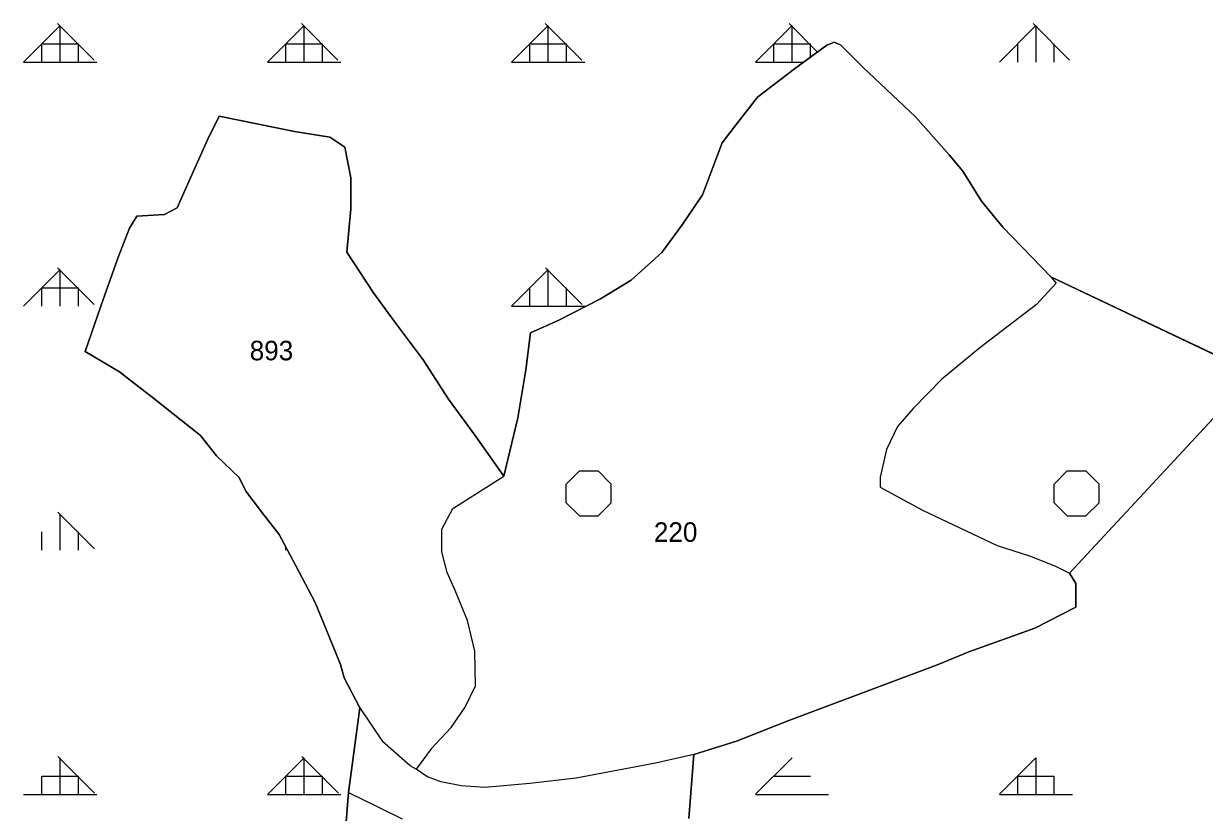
# Model space of a CAD drawing. Extents: x 410727 to 412947, y 4463506 to 4466382.
# Drawn here: x 412205.2 to 412447.2, y 4465932.2 to 4466093.7 of the extents above; entities that cross this region are included whole.
import ezdxf

# ---------------------------------------------------------------- set-up
doc = ezdxf.new("R2010")
doc.units = 0
for name, color, linetype in [('ADAKENARI', 7, 'Continuous'), ('KDS_PARSEL_NO', 7, 'Continuous'), ('KDS_PL', 7, 'Continuous'), ('PL_AYA_ORMAN', 7, 'Continuous'), ('PL_KA_TARIM_DIGER', 7, 'Continuous'), ('TR_ORMAN', 7, 'Continuous'), ('TR_TARIMALANI', 7, 'Continuous')]:
    doc.layers.add(name, color=color, linetype=linetype)

msp = doc.modelspace()

# ---------------------------------------------------------------- linework, layer by layer
at = {"layer": 'ADAKENARI'}
for p, q in [((412369.78, 4466089.3), (412363.17, 4466084.46)), ((412371.39, 4466089.94), (412369.78, 4466089.3)), ((412372.67, 4466089.3), (412371.39, 4466089.94)), ((412377.18, 4466084.78), (412372.67, 4466089.3)), ((412363.17, 4466084.46), (412355.6, 4466078.65)), ((412387.98, 4466074.61), (412377.18, 4466084.78)), ((412355.6, 4466078.65), (412350.77, 4466072.51)), ((412245.23, 4466074.74), (412242.83, 4466069.93)), ((412260.68, 4466071.65), (412245.23, 4466074.74)), ((412394.9, 4466066.87), (412387.98, 4466074.61)), ((412267.9, 4466070.44), (412260.68, 4466071.65)), ((412350.77, 4466072.51), (412348.35, 4466069.29)), ((412242.83, 4466069.93), (412239.91, 4466063.39)), ((412270.97, 4466068.4), (412267.9, 4466070.44)), ((412348.35, 4466069.29), (412344.33, 4466058.64)), ((412272.25, 4466062.11), (412270.97, 4466068.4)), ((412397.64, 4466063.48), (412394.9, 4466066.87)), ((412239.91, 4466063.39), (412236.64, 4466055.99)), ((412272.25, 4466055.81), (412272.25, 4466062.11)), ((412401.5, 4466057.35), (412397.64, 4466063.48)), ((412344.33, 4466058.64), (412342.88, 4466056.54)), ((412405.85, 4466052.02), (412401.5, 4466057.35)), ((412236.64, 4466055.99), (412234.07, 4466054.61)), ((412271.41, 4466046.93), (412272.25, 4466055.81)), ((412342.88, 4466056.54), (412340.14, 4466052.5)), ((412228.4, 4466054.27), (412226.85, 4466051.86)), ((412234.07, 4466054.61), (412228.4, 4466054.27)), ((412340.14, 4466052.5), (412335.95, 4466046.86)), ((412226.85, 4466051.86), (412224.45, 4466045.67)), ((412415.68, 4466041.85), (412405.85, 4466052.02)), ((412224.45, 4466045.67), (412221.02, 4466035.86)), ((412276.88, 4466038.56), (412271.41, 4466046.93)), ((412335.95, 4466046.86), (412329.67, 4466041.21)), ((412329.67, 4466041.21), (412323.39, 4466037.33)), ((412454.95, 4466023.24), (412415.68, 4466041.85)), ((412281.13, 4466032.78), (412276.88, 4466038.56)), ((412221.02, 4466035.86), (412217.75, 4466026.57)), ((412323.39, 4466037.33), (412314.85, 4466032.98)), ((412314.85, 4466032.98), (412309.05, 4466030.4)), ((412287.05, 4466024.87), (412281.13, 4466032.78)), ((412309.05, 4466030.4), (412308.09, 4466022.81)), ((412217.75, 4466026.57), (412224.79, 4466022.44)), ((412292.22, 4466016.8), (412287.05, 4466024.87)), ((412224.79, 4466022.44), (412231.83, 4466016.93)), ((412224.79, 4466022.44), (412231.83, 4466016.93)), ((412308.09, 4466022.81), (412306.48, 4466012.97)), ((412231.83, 4466016.93), (412241.45, 4466009.36)), ((412297.84, 4466009.19), (412292.22, 4466016.8)), ((412306.48, 4466012.97), (412303.58, 4466001.03)), ((412419.54, 4465981.17), (412449.06, 4466012.92)), ((412241.45, 4466009.36), (412244.71, 4466005.23)), ((412303.58, 4466001.03), (412297.84, 4466009.19)), ((412244.71, 4466005.23), (412249.35, 4466000.76)), ((412249.35, 4466000.76), (412250.72, 4465998)), ((412250.72, 4465998), (412254.13, 4465993.44)), ((412254.13, 4465993.44), (412257.52, 4465989.08)), ((412257.52, 4465989.08), (412260.9, 4465982.79)), ((412260.9, 4465982.79), (412264.92, 4465975.2)), ((412420.83, 4465979.08), (412419.54, 4465981.17)), ((412420.83, 4465974.24), (412420.83, 4465979.08)), ((412264.92, 4465975.2), (412268.47, 4465966.49)), ((412412.45, 4465969.88), (412420.83, 4465974.24)), ((412398.92, 4465965.04), (412412.45, 4465969.88)), ((412268.47, 4465966.49), (412270.08, 4465962.45)), ((412392.64, 4465962.46), (412398.92, 4465965.04)), ((412270.08, 4465962.45), (412270.88, 4465959.71)), ((412377.83, 4465956.97), (412392.64, 4465962.46)), ((412270.88, 4465959.71), (412274.1, 4465953.58)), ((412362.04, 4465951), (412377.83, 4465956.97)), ((412274.1, 4465953.58), (412271.74, 4465936.28)), ((412351.25, 4465946.8), (412362.04, 4465951)), ((412342.55, 4465944.06), (412351.25, 4465946.8)), ((412341.52, 4465930.96), (412342.55, 4465944.06)), ((412271.74, 4465936.28), (412271.14, 4465928.57))]:
    msp.add_line(p, q, dxfattribs=at)
at = {"layer": 'KDS_PL'}
for p, q in [((412363.17, 4466084.46), (412369.78, 4466089.3)), ((412369.78, 4466089.3), (412371.39, 4466089.94)), ((412371.39, 4466089.94), (412372.67, 4466089.3)), ((412372.67, 4466089.3), (412377.18, 4466084.78)), ((412355.6, 4466078.65), (412363.17, 4466084.46)), ((412377.18, 4466084.78), (412387.98, 4466074.61)), ((412350.77, 4466072.51), (412355.6, 4466078.65)), ((412242.83, 4466069.93), (412245.23, 4466074.74)), ((412245.23, 4466074.74), (412260.68, 4466071.65)), ((412387.98, 4466074.61), (412394.9, 4466066.87)), ((412260.68, 4466071.65), (412267.9, 4466070.44)), ((412348.35, 4466069.29), (412350.77, 4466072.51)), ((412239.91, 4466063.39), (412242.83, 4466069.93)), ((412267.9, 4466070.44), (412270.97, 4466068.4)), ((412344.33, 4466058.64), (412348.35, 4466069.29)), ((412270.97, 4466068.4), (412272.25, 4466062.11)), ((412394.9, 4466066.87), (412397.64, 4466063.48)), ((412236.64, 4466055.99), (412239.91, 4466063.39)), ((412272.25, 4466062.11), (412272.25, 4466055.81)), ((412397.64, 4466063.48), (412401.5, 4466057.35)), ((412342.88, 4466056.54), (412344.33, 4466058.64)), ((412401.5, 4466057.35), (412405.85, 4466052.02)), ((412234.07, 4466054.61), (412236.64, 4466055.99)), ((412272.25, 4466055.81), (412271.41, 4466046.93)), ((412340.14, 4466052.5), (412342.88, 4466056.54)), ((412226.85, 4466051.86), (412228.4, 4466054.27)), ((412228.4, 4466054.27), (412234.07, 4466054.61)), ((412335.95, 4466046.86), (412340.14, 4466052.5)), ((412224.45, 4466045.67), (412226.85, 4466051.86)), ((412405.85, 4466052.02), (412415.68, 4466041.85)), ((412221.02, 4466035.86), (412224.45, 4466045.67)), ((412271.41, 4466046.93), (412276.88, 4466038.56)), ((412329.67, 4466041.21), (412335.95, 4466046.86)), ((412323.39, 4466037.33), (412329.67, 4466041.21)), ((412416.8, 4466040.56), (412412.78, 4466036.21)), ((412415.68, 4466041.85), (412416.8, 4466040.56)), ((412276.88, 4466038.56), (412281.13, 4466032.78)), ((412217.75, 4466026.57), (412221.02, 4466035.86)), ((412314.85, 4466032.98), (412323.39, 4466037.33)), ((412412.78, 4466036.21), (412401.18, 4466027.33)), ((412309.05, 4466030.4), (412314.85, 4466032.98)), ((412281.13, 4466032.78), (412287.05, 4466024.87)), ((412308.09, 4466022.81), (412309.05, 4466030.4)), ((412224.79, 4466022.44), (412217.75, 4466026.57)), ((412401.18, 4466027.33), (412393.29, 4466020.87)), ((412287.05, 4466024.87), (412292.22, 4466016.8)), ((412231.83, 4466016.93), (412224.79, 4466022.44)), ((412306.48, 4466012.97), (412308.09, 4466022.81)), ((412393.29, 4466020.87), (412387.49, 4466014.9)), ((412241.45, 4466009.36), (412231.83, 4466016.93)), ((412292.22, 4466016.8), (412297.84, 4466009.19)), ((412387.49, 4466014.9), (412384.27, 4466011.19)), ((412303.58, 4466001.03), (412306.48, 4466012.97)), ((412384.27, 4466011.19), (412382.02, 4466006.51)), ((412244.71, 4466005.23), (412241.45, 4466009.36)), ((412297.84, 4466009.19), (412303.58, 4466001.03)), ((412382.02, 4466006.51), (412380.73, 4466000.86)), ((412249.35, 4466000.76), (412244.71, 4466005.23)), ((412250.72, 4465998), (412249.35, 4466000.76)), ((412298.75, 4465997.96), (412303.58, 4466001.03)), ((412380.73, 4466000.86), (412380.73, 4465998.76)), ((412250.72, 4465998), (412254.13, 4465993.44)), ((412293.11, 4465994.41), (412298.75, 4465997.96)), ((412380.73, 4465998.76), (412389.42, 4465994.09)), ((412290.85, 4465990.21), (412293.11, 4465994.41)), ((412257.52, 4465989.08), (412254.13, 4465993.44)), ((412389.42, 4465994.09), (412404.72, 4465986.82)), ((412290.85, 4465985.53), (412290.85, 4465990.21)), ((412260.9, 4465982.79), (412257.52, 4465989.08)), ((412291.98, 4465981.34), (412290.85, 4465985.53)), ((412404.72, 4465986.82), (412411.33, 4465984.73)), ((412411.33, 4465984.73), (412416.64, 4465982.63)), ((412264.92, 4465975.2), (412260.9, 4465982.79)), ((412416.64, 4465982.63), (412419.54, 4465981.17)), ((412293.59, 4465977.62), (412291.98, 4465981.34)), ((412419.54, 4465981.17), (412420.83, 4465979.08)), ((412296.17, 4465971.49), (412293.59, 4465977.62)), ((412420.83, 4465979.08), (412420.83, 4465975.69)), ((412268.47, 4465966.49), (412264.92, 4465975.2)), ((412420.83, 4465975.69), (412420.83, 4465974.24)), ((412420.83, 4465974.24), (412412.45, 4465969.88)), ((412297.62, 4465965.2), (412296.17, 4465971.49)), ((412412.45, 4465969.88), (412398.92, 4465965.04)), ((412270.08, 4465962.45), (412268.47, 4465966.49)), ((412297.78, 4465958.1), (412297.62, 4465965.2)), ((412398.92, 4465965.04), (412392.64, 4465962.46)), ((412270.08, 4465962.45), (412270.88, 4465959.71)), ((412392.64, 4465962.46), (412377.83, 4465956.97)), ((412270.88, 4465959.71), (412274.1, 4465953.58)), ((412295.69, 4465953.74), (412297.78, 4465958.1)), ((412377.83, 4465956.97), (412362.04, 4465951)), ((412274.1, 4465953.58), (412278.72, 4465946.73)), ((412292.79, 4465949.54), (412295.69, 4465953.74)), ((412362.04, 4465951), (412351.25, 4465946.8)), ((412288.68, 4465945.18), (412292.79, 4465949.54)), ((412284.38, 4465941.74), (412278.72, 4465946.73)), ((412351.25, 4465946.8), (412342.55, 4465944.06)), ((412288.68, 4465945.18), (412285.59, 4465941.05)), ((412342.55, 4465944.06), (412334.66, 4465942.28)), ((412285.59, 4465941.05), (412284.38, 4465941.74)), ((412287.79, 4465939.54), (412285.59, 4465941.05)), ((412334.66, 4465942.28), (412318.39, 4465939.22)), ((412290.69, 4465938.41), (412287.79, 4465939.54)), ((412318.39, 4465939.22), (412308.89, 4465938.09)), ((412271.14, 4465928.57), (412271.74, 4465936.28)), ((412271.74, 4465936.28), (412277.63, 4465933.41)), ((412294.88, 4465937.6), (412290.69, 4465938.41)), ((412299.71, 4465937.28), (412294.88, 4465937.6)), ((412308.89, 4465938.09), (412299.71, 4465937.28)), ((412277.63, 4465933.41), (412282.77, 4465930.84))]:
    msp.add_line(p, q, dxfattribs=at)
at = {"layer": 'PL_AYA_ORMAN'}
for points in [[(412271.14, 4465928.57), (412271.74, 4465936.28), (412274.1, 4465953.58), (412270.88, 4465959.71), (412270.08, 4465962.45), (412268.47, 4465966.49), (412264.92, 4465975.2), (412260.9, 4465982.79), (412257.52, 4465989.08), (412254.13, 4465993.44), (412250.72, 4465998), (412249.35, 4466000.76), (412244.71, 4466005.23), (412241.45, 4466009.36), (412231.83, 4466016.93), (412224.79, 4466022.44), (412217.75, 4466026.57), (412221.02, 4466035.86), (412224.45, 4466045.67), (412226.85, 4466051.86), (412228.4, 4466054.27), (412234.07, 4466054.61), (412236.64, 4466055.99), (412239.91, 4466063.39), (412242.83, 4466069.93), (412245.23, 4466074.74), (412260.68, 4466071.65), (412267.9, 4466070.44), (412270.97, 4466068.4), (412272.25, 4466062.11), (412272.25, 4466055.81), (412271.41, 4466046.93), (412276.88, 4466038.56), (412281.13, 4466032.78), (412287.05, 4466024.87), (412292.22, 4466016.8), (412297.84, 4466009.19), (412303.58, 4466001.03), (412306.48, 4466012.97), (412308.09, 4466022.81), (412309.05, 4466030.4), (412314.85, 4466032.98), (412323.39, 4466037.33), (412329.67, 4466041.21), (412335.95, 4466046.86), (412340.14, 4466052.5), (412342.88, 4466056.54), (412344.33, 4466058.64), (412348.35, 4466069.29), (412350.77, 4466072.51), (412355.6, 4466078.65), (412363.17, 4466084.46), (412369.78, 4466089.3), (412371.39, 4466089.94), (412372.67, 4466089.3), (412377.18, 4466084.78), (412387.98, 4466074.61), (412394.9, 4466066.87), (412397.64, 4466063.48), (412401.5, 4466057.35), (412405.85, 4466052.02), (412415.68, 4466041.85), (412454.95, 4466023.24)], [(412449.06, 4466012.92), (412419.54, 4465981.17), (412420.83, 4465979.08), (412420.83, 4465974.24), (412412.45, 4465969.88), (412398.92, 4465965.04), (412392.64, 4465962.46), (412377.83, 4465956.97), (412362.04, 4465951), (412351.25, 4465946.8), (412342.55, 4465944.06), (412341.52, 4465930.96)]]:
    msp.add_lwpolyline(points, dxfattribs=at)
at = {"layer": 'PL_KA_TARIM_DIGER'}
for points in [[(412271.14, 4465928.57), (412271.74, 4465936.28), (412274.1, 4465953.58), (412270.88, 4465959.71), (412270.08, 4465962.45), (412268.47, 4465966.49), (412264.92, 4465975.2), (412260.9, 4465982.79), (412257.52, 4465989.08), (412254.13, 4465993.44), (412250.72, 4465998), (412249.35, 4466000.76), (412244.71, 4466005.23), (412241.45, 4466009.36), (412231.83, 4466016.93), (412224.79, 4466022.44), (412217.75, 4466026.57), (412221.02, 4466035.86), (412224.45, 4466045.67), (412226.85, 4466051.86), (412228.4, 4466054.27), (412234.07, 4466054.61), (412236.64, 4466055.99), (412239.91, 4466063.39), (412242.83, 4466069.93), (412245.23, 4466074.74), (412260.68, 4466071.65), (412267.9, 4466070.44), (412270.97, 4466068.4), (412272.25, 4466062.11), (412272.25, 4466055.81), (412271.41, 4466046.93), (412276.88, 4466038.56), (412281.13, 4466032.78), (412287.05, 4466024.87), (412292.22, 4466016.8), (412297.84, 4466009.19), (412303.58, 4466001.03), (412306.48, 4466012.97), (412308.09, 4466022.81), (412309.05, 4466030.4), (412314.85, 4466032.98), (412323.39, 4466037.33), (412329.67, 4466041.21), (412335.95, 4466046.86), (412340.14, 4466052.5), (412342.88, 4466056.54), (412344.33, 4466058.64), (412348.35, 4466069.29), (412350.77, 4466072.51), (412355.6, 4466078.65), (412363.17, 4466084.46), (412369.78, 4466089.3), (412371.39, 4466089.94), (412372.67, 4466089.3), (412377.18, 4466084.78), (412387.98, 4466074.61), (412394.9, 4466066.87), (412397.64, 4466063.48), (412401.5, 4466057.35), (412405.85, 4466052.02), (412415.68, 4466041.85), (412454.95, 4466023.24)], [(412449.06, 4466012.92), (412419.54, 4465981.17), (412420.83, 4465979.08), (412420.83, 4465974.24), (412412.45, 4465969.88), (412398.92, 4465965.04), (412392.64, 4465962.46), (412377.83, 4465956.97), (412362.04, 4465951), (412351.25, 4465946.8), (412342.55, 4465944.06), (412341.52, 4465930.96)]]:
    msp.add_lwpolyline(points, dxfattribs=at)
at = {"layer": 'TR_ORMAN'}
for p, q in [((412219.6, 4466086.23), (412212.1, 4466093.72)), ((412219.6, 4466086.23), (412212.1, 4466093.72)), ((412269.59, 4466086.23), (412262.09, 4466093.72)), ((412269.59, 4466086.23), (412262.09, 4466093.72)), ((412319.58, 4466086.23), (412312.09, 4466093.72)), ((412319.58, 4466086.23), (412312.09, 4466093.72)), ((412367.89, 4466087.91), (412362.08, 4466093.72)), ((412367.89, 4466087.91), (412362.08, 4466093.72)), ((412419.57, 4466086.23), (412412.07, 4466093.72)), ((412205.16, 4466085.83), (412212.66, 4466093.33)), ((412212.67, 4466085.86), (412212.67, 4466093.36)), ((412255.16, 4466085.84), (412262.66, 4466093.34)), ((412255.16, 4466085.84), (412262.66, 4466093.34)), ((412262.67, 4466085.86), (412262.67, 4466093.36)), ((412262.67, 4466085.86), (412262.67, 4466093.36)), ((412305.16, 4466085.85), (412312.66, 4466093.35)), ((412305.16, 4466085.85), (412312.66, 4466093.35)), ((412312.67, 4466085.86), (412312.67, 4466093.36)), ((412355.16, 4466085.85), (412362.66, 4466093.35)), ((412355.16, 4466085.85), (412362.66, 4466093.35)), ((412362.67, 4466085.86), (412362.67, 4466093.36)), ((412362.67, 4466085.86), (412362.67, 4466093.36)), ((412405.16, 4466085.86), (412412.66, 4466093.36)), ((412405.16, 4466085.86), (412412.66, 4466093.36)), ((412412.67, 4466085.86), (412412.67, 4466093.36)), ((412208.92, 4466085.86), (412208.92, 4466089.61)), ((412208.92, 4466089.61), (412216.42, 4466089.61)), ((412216.42, 4466085.86), (412216.42, 4466089.61)), ((412258.92, 4466085.86), (412258.92, 4466089.61)), ((412258.92, 4466085.86), (412258.92, 4466089.61)), ((412258.92, 4466089.61), (412266.42, 4466089.61)), ((412266.42, 4466085.86), (412266.42, 4466089.61)), ((412266.42, 4466085.86), (412266.42, 4466089.61)), ((412308.92, 4466085.86), (412308.92, 4466089.61)), ((412308.92, 4466085.86), (412308.92, 4466089.61)), ((412308.92, 4466089.61), (412316.42, 4466089.61)), ((412316.42, 4466085.86), (412316.42, 4466089.61)), ((412358.92, 4466085.86), (412358.92, 4466089.61)), ((412358.92, 4466085.86), (412358.92, 4466089.61)), ((412358.92, 4466089.61), (412366.42, 4466089.61)), ((412366.42, 4466086.84), (412366.42, 4466089.61)), ((412366.42, 4466086.84), (412366.42, 4466089.61)), ((412408.92, 4466085.86), (412408.92, 4466089.61)), ((412416.42, 4466085.86), (412416.42, 4466089.61)), ((412205.17, 4466085.86), (412220.17, 4466085.86)), ((412255.17, 4466085.86), (412270.17, 4466085.86)), ((412305.17, 4466085.86), (412320.17, 4466085.86)), ((412355.17, 4466085.86), (412365.09, 4466085.86)), ((412205.16, 4466035.84), (412212.66, 4466043.34)), ((412205.16, 4466035.84), (412212.66, 4466043.34)), ((412219.63, 4466036.2), (412212.13, 4466043.7)), ((412219.63, 4466036.2), (412212.13, 4466043.7)), ((412212.67, 4466035.86), (412212.67, 4466043.36)), ((412305.16, 4466035.85), (412312.66, 4466043.35)), ((412305.16, 4466035.85), (412312.66, 4466043.35)), ((412319.62, 4466036.2), (412312.12, 4466043.7)), ((412319.62, 4466036.2), (412312.12, 4466043.7)), ((412312.67, 4466035.86), (412312.67, 4466043.36)), ((412208.92, 4466035.86), (412208.92, 4466039.61)), ((412208.92, 4466039.61), (412216.42, 4466039.61)), ((412216.42, 4466035.86), (412216.42, 4466039.61)), ((412308.92, 4466035.86), (412308.92, 4466039.61)), ((412308.92, 4466035.86), (412308.92, 4466039.61)), ((412316.42, 4466035.86), (412316.42, 4466039.61)), ((412305.17, 4466035.86), (412320.17, 4466035.86)), ((412219.66, 4465986.18), (412212.16, 4465993.68)), ((412219.66, 4465986.18), (412212.16, 4465993.68)), ((412212.67, 4465985.86), (412212.67, 4465993.36)), ((412208.92, 4465985.86), (412208.92, 4465989.61)), ((412216.42, 4465985.86), (412216.42, 4465989.61)), ((412258.92, 4465985.86), (412258.92, 4465986.47)), ((412219.7, 4465936.15), (412212.2, 4465943.65)), ((412219.7, 4465936.15), (412212.2, 4465943.65)), ((412212.67, 4465935.86), (412212.67, 4465943.36)), ((412255.16, 4465935.86), (412262.66, 4465943.36)), ((412269.69, 4465936.15), (412262.19, 4465943.65)), ((412269.69, 4465936.15), (412262.19, 4465943.65)), ((412262.67, 4465935.86), (412262.67, 4465943.36)), ((412355.16, 4465935.88), (412362.66, 4465943.38)), ((412405.16, 4465935.88), (412412.66, 4465943.38)), ((412412.67, 4465935.86), (412412.67, 4465943.36)), ((412208.92, 4465935.86), (412208.92, 4465939.61)), ((412208.92, 4465939.61), (412216.42, 4465939.61)), ((412216.42, 4465935.86), (412216.42, 4465939.61)), ((412258.92, 4465935.86), (412258.92, 4465939.61)), ((412258.92, 4465939.61), (412266.42, 4465939.61)), ((412266.42, 4465935.86), (412266.42, 4465939.61)), ((412358.92, 4465939.61), (412366.42, 4465939.61)), ((412408.92, 4465935.86), (412408.92, 4465939.61)), ((412408.92, 4465939.61), (412416.42, 4465939.61)), ((412416.42, 4465935.86), (412416.42, 4465939.61)), ((412205.17, 4465935.86), (412220.17, 4465935.86)), ((412255.17, 4465935.86), (412270.17, 4465935.86)), ((412355.17, 4465935.86), (412370.17, 4465935.86)), ((412405.17, 4465935.86), (412420.17, 4465935.86))]:
    msp.add_line(p, q, dxfattribs=at)
at = {"layer": 'TR_TARIMALANI'}
for p, q in [((412316.37, 4465999.43), (412319.08, 4466002.13)), ((412316.37, 4465999.43), (412319.08, 4466002.13)), ((412319.08, 4466002.14), (412322.91, 4466002.14)), ((412325.62, 4465999.43), (412322.91, 4466002.13)), ((412416.37, 4465999.43), (412419.08, 4466002.13)), ((412419.08, 4466002.14), (412422.91, 4466002.14)), ((412425.62, 4465999.43), (412422.91, 4466002.13)), ((412316.37, 4465995.6), (412316.37, 4465999.43)), ((412325.62, 4465995.6), (412325.62, 4465999.43)), ((412416.37, 4465995.6), (412416.37, 4465999.43)), ((412425.62, 4465995.6), (412425.62, 4465999.43)), ((412319.08, 4465992.89), (412316.37, 4465995.59)), ((412322.91, 4465992.89), (412325.62, 4465995.59)), ((412322.91, 4465992.89), (412325.62, 4465995.59)), ((412419.08, 4465992.89), (412416.37, 4465995.59)), ((412422.91, 4465992.89), (412425.62, 4465995.59)), ((412319.08, 4465992.89), (412322.91, 4465992.89)), ((412419.08, 4465992.89), (412422.91, 4465992.89))]:
    msp.add_line(p, q, dxfattribs=at)

# ---------------------------------------------------------------- texts
at = {"layer": 'KDS_PARSEL_NO'}
for s, p in [('893', (412251.5, 4466024.77)), ('220', (412334.35, 4465987.59))]:
    msp.add_text(s, height=4, dxfattribs=at).set_placement(p)

doc.saveas('drawing.dxf')
